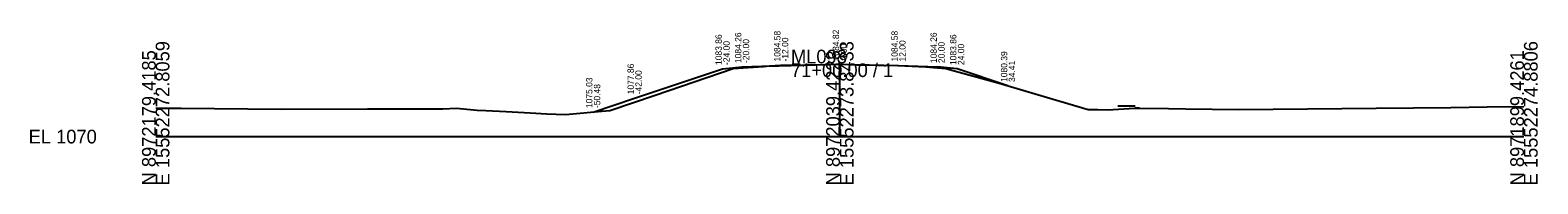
# Model space of a CAD drawing. Extents: x -26 to 14283, y -10 to 28.
# Drawn here: x 11974.3 to 12282.8, y -9.7 to 21.8 of the extents above; entities that cross this region are included whole.
import ezdxf

# ---------------------------------------------------------------- set-up
doc = ezdxf.new("R2010")
doc.units = 0
for name, color, linetype in [('Default', 7, 'Continuous'), ('dsn3DCenterLine', 7, 'Continuous'), ('dsn3DForeSlopeBarnRoofPoint', 7, 'Continuous'), ('dsn3DForeSlopeBreakLine', 7, 'Continuous'), ('dsn3DGroundLineIntercept', 7, 'Continuous'), ('dsn3DPavementTop', 7, 'Continuous'), ('dsn3DShoulderTop', 7, 'Continuous'), ('dsn3DSubgradeBreakLine', 7, 'Continuous'), ('dsn3DSubgradeHingePoint', 7, 'Continuous'), ('dsnGeopakCellCrossSection', 7, 'Continuous'), ('dsnXSEarthwork', 7, 'Continuous'), ('dsnXsExistingGround', 7, 'Continuous'), ('dsnXsSideSlopes', 7, 'Continuous'), ('dsnXsTextOffsetElevFinGrd', 7, 'Continuous'), ('SurPointsNonDTM', 7, 'Continuous'), ('SurSurveyPoints', 7, 'Continuous'), ('SurUtilityPoleCell', 7, 'Continuous')]:
    doc.layers.add(name, color=color, linetype=linetype)

msp = doc.modelspace()

# ---------------------------------------------------------------- linework, layer by layer
at = {"layer": 'Default'}
msp.add_lwpolyline([(12120, 14.26), (12120, 14.26), (12140, 14.82), (12152, 14.58), (12160, 14.26)], dxfattribs=at)
at = {"layer": 'dsnGeopakCellCrossSection'}
for p, q in [((12140, 0), (12140, 15)), ((12000, 0), (12140, 0)), ((12140, 0), (12280, 0))]:
    msp.add_line(p, q, dxfattribs=at)
at = {"layer": 'dsnXSEarthwork'}
msp.add_lwpolyline([(12120, 14.26), (12128, 14.58), (12140, 14.82), (12152, 14.58), (12160, 14.26)], dxfattribs=at)
at = {"layer": 'dsnXsExistingGround'}
msp.add_lwpolyline([(12000, 5.8), (12005.2, 5.79), (12025.67, 5.65), (12043.31, 5.69), (12058.75, 5.69), (12061.57, 5.79), (12065.81, 5.44), (12067.59, 5.34), (12071.7, 5.11), (12076.61, 4.84), (12080.01, 4.69), (12083.86, 4.53), (12091.31, 5.19), (12092.91, 5.34), (12102.24, 8.5), (12118.14, 13.93), (12124.32, 14.39), (12124.45, 14.4), (12124.52, 14.4), (12127.84, 14.6), (12138.03, 14.78), (12139.98, 14.81), (12143.46, 14.73), (12151.87, 14.53), (12156.16, 14.33), (12157.61, 14.26), (12159.14, 14.15), (12161.71, 13.96), (12172.59, 10.92), (12184.83, 7.32), (12190.83, 5.55), (12192.79, 5.53), (12194.83, 5.5), (12199.23, 5.73), (12200.9, 5.82), (12207.23, 5.72), (12210.8, 5.66), (12221.67, 5.54), (12249.78, 5.8), (12265.02, 5.96), (12272.49, 6.08), (12280, 6.13)], dxfattribs=at)
at = {"layer": 'dsnXsSideSlopes'}
for points in [[(12089.52, 5.03), (12098, 7.86), (12098, 7.86), (12098, 7.86), (12116, 13.86), (12116, 13.86), (12120, 14.26)], [(12174.41, 10.39), (12174.41, 10.39), (12164, 13.86), (12164, 13.86), (12160, 14.26)]]:
    msp.add_lwpolyline(points, dxfattribs=at)
at = {"layer": 'SurPointsNonDTM'}
msp.add_lwpolyline([(12201.35, 5.82), (12200.39, 5.82)], dxfattribs=at)
at = {"layer": 'SurSurveyPoints'}
msp.add_lwpolyline([(12201.27, 5.82), (12200.53, 5.82)], dxfattribs=at)
at = {"layer": 'SurUtilityPoleCell'}
msp.add_lwpolyline([(12196.9, 6.27), (12200.43, 6.27)], dxfattribs=at)

# ---------------------------------------------------------------- texts
msp.add_text('-', height=0.0001).set_placement((12000, 0))
at = {"layer": 'dsn3DCenterLine'}
msp.add_text('X', height=0.00781, dxfattribs=at).set_placement((12140, 14.81))
at = {"layer": 'dsn3DForeSlopeBarnRoofPoint'}
for p in [(12174.41, 10.38), (12098, 7.85)]:
    msp.add_text('X', height=0.00781, dxfattribs=at).set_placement(p)
at = {"layer": 'dsn3DForeSlopeBreakLine'}
for p in [(12116, 13.85), (12164, 13.85)]:
    msp.add_text('X', height=0.00781, dxfattribs=at).set_placement(p)
at = {"layer": 'dsn3DGroundLineIntercept'}
msp.add_text('X', height=0.00781, dxfattribs=at).set_placement((12089.51, 5.03))
at = {"layer": 'dsn3DPavementTop'}
for p in [(12128, 14.57), (12152, 14.57)]:
    msp.add_text('X', height=0.00781, dxfattribs=at).set_placement(p)
at = {"layer": 'dsn3DShoulderTop'}
for p in [(12120, 14.25), (12160, 14.25)]:
    msp.add_text('X', height=0.00781, dxfattribs=at).set_placement(p)
at = {"layer": 'dsn3DSubgradeBreakLine'}
for p in [(12128, 13.07), (12140, 13.31)]:
    msp.add_text('X', height=0.00781, dxfattribs=at).set_placement(p)
at = {"layer": 'dsn3DSubgradeHingePoint'}
for p in [(12112.57, 12.71), (12167.42, 12.71)]:
    msp.add_text('X', height=0.00781, dxfattribs=at).set_placement(p)
at = {"layer": 'dsnGeopakCellCrossSection'}
for s, p in [('E 15552272.8059', (12002.8, -10)), ('E 15552273.8433', (12142.8, -10)), ('E 15552274.8806', (12282.8, -10)), ('N 8972179.4185', (12000, -10)), ('N 8972039.4223', (12140, -10)), ('N 8971899.4261', (12280, -10))]:
    msp.add_text(s, height=2.8, rotation=90, dxfattribs=at).set_placement(p)
for s, p in [('ML093', (12130, 15)), ('71+00.00 / 1', (12130, 12.2)), ('EL 1070', (11974, -1.4))]:
    msp.add_text(s, height=2.8, dxfattribs=at).set_placement(p)
at = {"layer": 'dsnXsTextOffsetElevFinGrd'}
for s, p in [('1084.82', (12139.85, 15.62)), ('1084.82', (12139.85, 15.62)), ('1083.86', (12115.85, 14.66)), ('-24.00', (12117.45, 14.66)), ('1084.26', (12119.85, 15.06)), ('-20.00', (12121.45, 15.06)), ('1084.58', (12127.85, 15.38)), ('-12.00', (12129.45, 15.38)), ('0.00', (12141.45, 15.62)), ('0.00', (12141.45, 15.62)), ('1084.58', (12151.85, 15.38)), ('12.00', (12153.45, 15.38)), ('1084.26', (12159.85, 15.06)), ('20.00', (12161.45, 15.06)), ('1083.86', (12163.85, 14.66)), ('24.00', (12165.45, 14.66)), ('1080.39', (12174.26, 11.19)), ('1080.39', (12174.26, 11.19)), ('34.41', (12175.86, 11.19)), ('34.41', (12175.86, 11.19)), ('1077.86', (12097.85, 8.66)), ('-42.00', (12099.45, 8.66)), ('1075.03', (12089.37, 5.83)), ('1075.03', (12089.37, 5.83)), ('-50.48', (12090.97, 5.83)), ('-50.48', (12090.97, 5.83))]:
    msp.add_text(s, height=1.3, rotation=90, dxfattribs=at).set_placement(p)

doc.saveas('drawing.dxf')
